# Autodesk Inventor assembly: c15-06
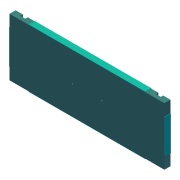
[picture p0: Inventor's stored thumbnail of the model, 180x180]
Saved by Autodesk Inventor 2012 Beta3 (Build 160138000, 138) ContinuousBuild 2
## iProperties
Created: 2011-02
Part Number: c15-06
Document SubType Name: Assembly
Designer: Beta-8540w
RuleStatus: InUse
Author: Beta-8540w
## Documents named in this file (4)
- C:\Inventor 2012 Essentials\Assemblies\Chapter 15\c15-06.iam
- C:\Inventor 2012 Essentials\Parts\Chapter 15\c15-21.ipt
- C:\Inventor 2012 Essentials\Parts\Chapter 15\c15-22.ipt
- C:\Inventor 2012 Essentials\Parts\Chapter 15\c15-23.ipt
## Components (5 placed, 3 different names)
1. c15-21:1 — Flush:3, Flush:6, Flush:9, Flush:12
2. c15-22:1 — Flush:3
3. c15-22:2 — Flush:6
4. c15-23:1 — Flush:9
5. c15-23:2 — Flush:12
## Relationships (4: Flush 4)
- Flush:3: c15-21:1 ↔ c15-22:1
- Flush:6: c15-21:1 ↔ c15-22:2
- Flush:9: c15-21:1 ↔ c15-23:1
- Flush:12: c15-21:1 ↔ c15-23:2
## Named parameters: drawer_width = 508 mm, drawer_height = 203.2 mm, pull_width = 76.2 mm, edge_band_thickness = 1 mm
